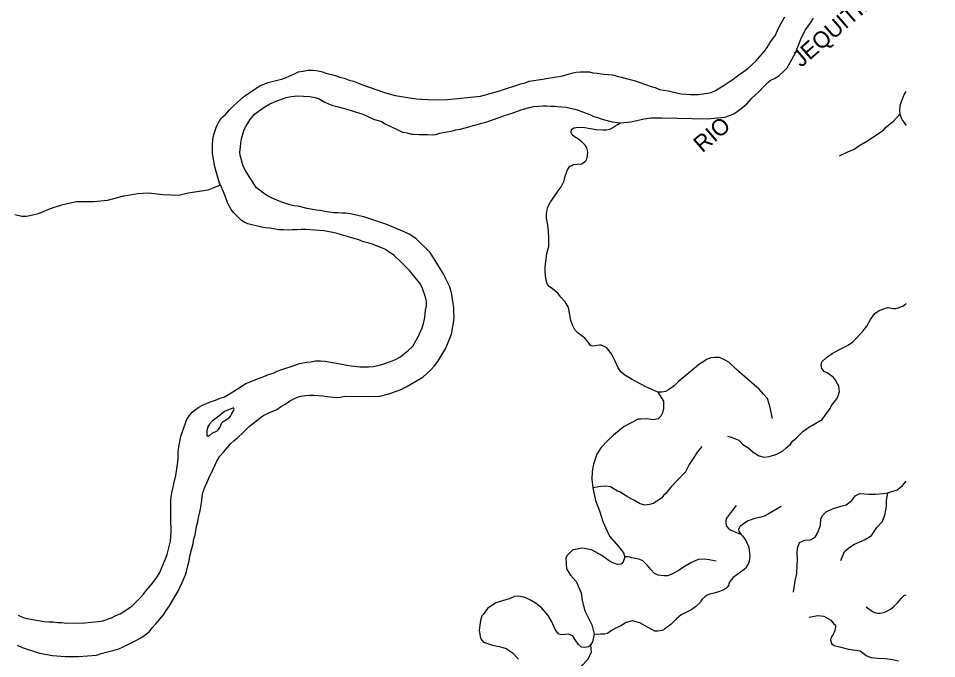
# Model space of a CAD drawing. Extents: x 436.3 to 500.4, y 8231 to 8286.4.
# Drawn here: x 489.18 to 500.37, y 8245.15 to 8252.95 of the extents above; entities that cross this region are included whole.
import ezdxf
from ezdxf.enums import TextEntityAlignment as Align

# ---------------------------------------------------------------- set-up
doc = ezdxf.new("R2010")
doc.units = 0
doc.header["$LTSCALE"] = 0.08
doc.linetypes.add('LONG_DASHED', pattern=[7.5, 6, -1.5])
doc.layers.add('2', color=7, linetype='Continuous', lineweight=25)
doc.layers.add('9', color=7, linetype='LONG_DASHED', lineweight=25)
doc.layers.add('61', color=7, linetype='Continuous')

msp = doc.modelspace()

# ---------------------------------------------------------------- linework, layer by layer
at = {"layer": '2'}
for points in [[(496.5165, 8251.6784), (496.6445, 8251.6907), (496.8052, 8251.7273), (496.8881, 8251.739), (497.0217, 8251.7391), (497.5766, 8251.728), (497.7884, 8251.7467), (497.8436, 8251.7691), (497.8975, 8251.7873), (497.9379, 8251.8145), (498.0231, 8251.8814), (498.0575, 8251.9115), (498.1127, 8251.974), (498.2117, 8252.0645), (498.2614, 8252.1183), (498.3108, 8252.1681), (498.3422, 8252.1953), (498.4006, 8252.2225), (498.4501, 8252.2543), (498.4995, 8252.2996), (498.5489, 8252.3494), (498.5894, 8252.4218), (498.6478, 8252.5304), (498.7153, 8252.6979), (498.7692, 8252.8064), (498.7962, 8252.8426), (498.8322, 8252.8969), (498.8682, 8252.9557)], [(498.2659, 8252.5483), (498.3064, 8252.5981), (498.3379, 8252.6525), (498.4053, 8252.7475), (498.4323, 8252.8018), (498.4548, 8252.8561), (498.4863, 8252.9149)], [(498.4863, 8252.9149), (498.5178, 8252.9692)], [(491.6412, 8250.9216), (491.6325, 8250.942), (491.5734, 8251.1435), (491.5464, 8251.3042), (491.5462, 8251.4128), (491.5506, 8251.4671), (491.5595, 8251.5214), (491.5729, 8251.5712), (491.5908, 8251.6209), (491.6132, 8251.6752), (491.6491, 8251.7295), (491.7029, 8251.7793), (491.7523, 8251.8381), (491.7927, 8251.8788), (491.8466, 8251.924), (491.923, 8251.9963), (492.0647, 8252.0935), (492.1208, 8252.1274), (492.1703, 8252.15), (492.2243, 8252.1681), (492.3864, 8252.2087), (492.4359, 8252.2267), (492.4899, 8252.2493), (492.5439, 8252.2764), (492.5935, 8252.299), (492.652, 8252.308), (492.7061, 8252.3216), (492.7718, 8252.3215), (492.8318, 8252.3123), (492.8862, 8252.2988), (492.9403, 8252.2807), (492.9943, 8252.2671), (493.0439, 8252.2535), (493.098, 8252.2353), (493.152, 8252.2217), (493.2106, 8252.1991), (493.2647, 8252.1854), (493.3232, 8252.1628), (493.3728, 8252.1401), (493.6432, 8252.0494), (493.7731, 8252.0111), (494.027, 8251.9716), (494.2371, 8251.9599), (494.4079, 8251.9644), (494.8116, 8252.0037), (494.8555, 8252.0172), (495.0313, 8252.063), (495.3014, 8252.1531), (495.3555, 8252.1667), (495.405, 8252.1848), (495.5716, 8252.212), (495.6122, 8252.2165), (495.8148, 8252.2528), (495.8688, 8252.2664), (495.9228, 8252.2846), (495.9769, 8252.2936), (496.0309, 8252.2982), (496.1389, 8252.2982), (496.1794, 8252.2892), (496.2334, 8252.2846), (496.3145, 8252.2711), (496.418, 8252.262), (496.4765, 8252.2485), (496.526, 8252.2349), (496.6339, 8252.2078), (496.6834, 8252.1942), (496.8904, 8252.1218), (496.9398, 8252.1082), (496.9938, 8252.0856), (497.0972, 8252.0675), (497.1467, 8252.054), (497.2007, 8252.0449), (497.2546, 8252.0314), (497.3707, 8252.0228), (497.4697, 8252.0229), (497.5526, 8252.0345), (497.6217, 8252.0485), (497.6746, 8252.074), (497.7806, 8252.136), (497.8884, 8252.2085), (497.9423, 8252.2493), (498.0682, 8252.3384), (498.1715, 8252.4351), (498.221, 8252.4895), (498.2659, 8252.5483)], [(492.443, 8251.9884), (492.5052, 8252), (492.5836, 8252.0069), (492.6551, 8252.0045), (492.7335, 8251.9975), (492.7958, 8251.9881), (492.8465, 8251.9719)], [(500, 8252.0616), (499.9877, 8252.0459), (499.9745, 8252.0268), (499.9635, 8251.9944), (499.9417, 8251.946), (499.92, 8251.8849), (499.9184, 8251.8224), (499.9215, 8251.7817)], [(491.5762, 8247.5104), (491.5986, 8247.5554), (491.6345, 8247.6139), (491.6795, 8247.6633), (491.7693, 8247.7713), (491.8052, 8247.8028), (491.8591, 8247.8477), (491.913, 8247.8972), (491.9984, 8247.9827), (492.1583, 8248.1069), (492.2231, 8248.14), (492.331, 8248.1848), (492.3759, 8248.2163), (492.4298, 8248.2478), (492.4838, 8248.2837), (492.5377, 8248.3152), (492.5917, 8248.3376), (492.6232, 8248.3465), (492.6772, 8248.3554), (492.7312, 8248.3598), (492.7807, 8248.3597), (492.8887, 8248.3504), (492.9427, 8248.3412), (493.0508, 8248.3319), (493.1003, 8248.3363), (493.1543, 8248.3452), (493.5325, 8248.3441), (493.5866, 8248.3484), (493.6946, 8248.3752), (493.7982, 8248.411), (493.8522, 8248.4334), (493.9062, 8248.4603), (494.108, 8248.5762), (494.2077, 8248.6671), (494.2526, 8248.7167), (494.2931, 8248.7708), (494.3874, 8248.9332), (494.4143, 8248.9919), (494.4592, 8249.1004), (494.4859, 8249.2632), (494.4903, 8249.3174), (494.4857, 8249.3717), (494.4856, 8249.426), (494.4764, 8249.4758), (494.4718, 8249.5302), (494.4627, 8249.5845), (494.4491, 8249.6389), (494.4354, 8249.6887), (494.354, 8249.8518), (494.1961, 8250.0958), (494.025, 8250.2674), (493.9418, 8250.3209), (493.8799, 8250.3507), (493.6589, 8250.4416), (493.3885, 8250.5325), (493.3344, 8250.5462), (493.2803, 8250.5553), (493.2262, 8250.569), (493.1722, 8250.5781), (493.1316, 8250.5782), (493.0776, 8250.5828), (493.0235, 8250.5829), (492.9695, 8250.5875), (492.9154, 8250.5966), (492.8614, 8250.6103), (492.8073, 8250.6149), (492.6992, 8250.6331), (492.5911, 8250.6604), (492.5371, 8250.665), (492.4876, 8250.6786), (492.438, 8250.6968), (492.3795, 8250.715), (492.2714, 8250.7604), (492.2173, 8250.7876), (492.1678, 8250.8193), (492.1137, 8250.8601), (492.0777, 8250.8918), (491.9532, 8251.089), (491.9242, 8251.1409), (491.9106, 8251.1771), (491.8835, 8251.2858), (491.8789, 8251.322), (491.8878, 8251.3808), (491.8922, 8251.4351), (491.9011, 8251.4849), (491.9145, 8251.5392), (491.9324, 8251.598), (491.9503, 8251.6342), (492.0041, 8251.7202), (492.0582, 8251.785), (492.1295, 8251.8382), (492.1756, 8251.8706), (492.2448, 8251.9099), (492.3208, 8251.9422), (492.443, 8251.9884)], [(492.8465, 8251.9719), (492.9066, 8251.9348), (492.9584, 8251.9095), (493.0124, 8251.8913), (493.062, 8251.8777), (493.1702, 8251.8505), (493.2738, 8251.8142), (493.3234, 8251.8005), (493.3775, 8251.7824), (493.4316, 8251.7597), (493.5082, 8251.7234), (493.6035, 8251.6933), (493.6497, 8251.6655), (493.7021, 8251.6417), (493.8103, 8251.5873), (493.8599, 8251.5646), (493.9185, 8251.5555), (493.9726, 8251.5419), (493.9951, 8251.5418), (494.0629, 8251.5373), (494.1664, 8251.5372), (494.2204, 8251.5326), (494.2655, 8251.5371), (494.3151, 8251.5507), (494.4007, 8251.5687), (494.4547, 8251.5778), (494.5088, 8251.5913), (494.5629, 8251.6004), (494.671, 8251.6275), (494.7205, 8251.6456), (494.7701, 8251.6592), (494.8286, 8251.6727), (494.8782, 8251.6863), (495.0397, 8251.7418), (495.0899, 8251.7633), (495.1439, 8251.7814), (495.198, 8251.795), (495.3061, 8251.8358), (495.4051, 8251.863), (495.4592, 8251.8766), (495.5718, 8251.8857), (495.6168, 8251.8857), (495.6708, 8251.8811), (495.7204, 8251.8811), (495.7519, 8251.8766), (495.8554, 8251.8676), (495.905, 8251.8585), (495.959, 8251.8449), (495.9905, 8251.8359), (496.1416, 8251.778), (496.1931, 8251.7543), (496.2246, 8251.7453), (496.3052, 8251.7201), (496.4159, 8251.6922), (496.5081, 8251.6784), (496.5165, 8251.6784)], [(499.9215, 8251.7817), (499.9371, 8251.7378), (499.9543, 8251.705), (499.9735, 8251.6818), (499.9867, 8251.6627), (500, 8251.6475)], [(492.1418, 8250.4076), (491.9754, 8250.4486), (491.9303, 8250.4666), (491.8987, 8250.4893), (491.8492, 8250.5346), (491.7996, 8250.5844), (491.7725, 8250.6206), (491.7364, 8250.6885), (491.7138, 8250.7519), (491.6862, 8250.8164), (491.6412, 8250.9216)], [(490.9292, 8246.2564), (490.9741, 8246.3642), (490.9921, 8246.4181), (491.0326, 8246.5799), (491.0416, 8246.6877), (491.0416, 8246.7417), (491.0371, 8246.7956), (491.0371, 8247.0654), (491.0415, 8247.1194), (491.0505, 8247.1689), (491.064, 8247.2228), (491.0729, 8247.2768), (491.0999, 8247.3803), (491.1088, 8247.4343), (491.1133, 8247.4883), (491.1222, 8247.5423), (491.1267, 8247.5963), (491.1266, 8247.6504), (491.1311, 8247.7044), (491.1579, 8247.8575), (491.2358, 8248.073), (491.252, 8248.0962), (491.2969, 8248.1502), (491.3328, 8248.1818), (491.3777, 8248.2133), (491.4226, 8248.2358), (491.5304, 8248.2808), (491.5843, 8248.2987), (491.6382, 8248.3212), (491.6922, 8248.3392), (491.7416, 8248.3662), (491.7955, 8248.3977), (491.9527, 8248.5012), (492.1251, 8248.5719), (492.1729, 8248.5865), (492.2268, 8248.609), (492.2853, 8248.6269), (492.3347, 8248.6494), (492.3887, 8248.6718), (492.4381, 8248.6898), (492.4921, 8248.7032), (492.5955, 8248.7391), (492.645, 8248.7526), (492.6945, 8248.7615), (492.7485, 8248.7659), (492.8025, 8248.7793), (492.861, 8248.7792), (492.915, 8248.7745), (493.1267, 8248.7379), (493.1807, 8248.7242), (493.2347, 8248.715), (493.3428, 8248.7057), (493.4509, 8248.7054), (493.5049, 8248.7098), (493.559, 8248.7187), (493.6085, 8248.7321), (493.7165, 8248.7679), (493.775, 8248.7948), (493.829, 8248.8218), (493.928, 8248.9028), (493.9864, 8248.9569), (494.0566, 8249.077), (494.0762, 8249.1285), (494.0986, 8249.1781), (494.1165, 8249.2324), (494.1299, 8249.2866), (494.1388, 8249.3409), (494.1432, 8249.3951), (494.1521, 8249.4494), (494.152, 8249.5037), (494.1429, 8249.5535), (494.1066, 8249.6576), (494.0795, 8249.712), (494.0524, 8249.7483), (493.9467, 8249.8783), (493.838, 8249.9897), (493.7595, 8250.0615), (493.6957, 8250.1065), (493.6461, 8250.1383), (493.6055, 8250.1565), (493.5514, 8250.1747), (493.4973, 8250.1974), (493.4387, 8250.2156), (493.3846, 8250.2293), (493.3305, 8250.252), (493.2269, 8250.2793), (493.1728, 8250.2975), (493.1187, 8250.3112), (493.0646, 8250.3294), (493.0106, 8250.343), (492.9025, 8250.3613), (492.6818, 8250.3797), (492.6278, 8250.3798), (492.5738, 8250.3753), (492.5198, 8250.3754)], [(492.5198, 8250.3754), (492.4658, 8250.371), (492.4118, 8250.3756), (492.3578, 8250.3756), (492.2453, 8250.3939), (492.1913, 8250.3985), (492.1418, 8250.4076)], [(491.419, 8247.1281), (491.428, 8247.1731), (491.4505, 8247.2361), (491.4774, 8247.29), (491.4999, 8247.3485), (491.5537, 8247.4564), (491.5762, 8247.5104)], [(489.1674, 8245.3117), (489.2259, 8245.2848), (489.4371, 8245.213), (489.5945, 8245.1862), (489.7517, 8245.1729), (489.9135, 8245.173), (490.1339, 8245.1892), (490.1876, 8245.2092), (490.3493, 8245.2498), (490.4032, 8245.2678), (490.4571, 8245.2903), (490.6189, 8245.3713), (490.6728, 8245.4028), (490.7267, 8245.4388), (490.7761, 8245.4792), (490.8121, 8245.5241), (490.857, 8245.5736), (490.9469, 8245.6814), (490.9829, 8245.7353), (491.0234, 8245.7892), (491.1313, 8245.9778), (491.1923, 8246.111), (491.2167, 8246.1709), (491.2347, 8246.2248), (491.2437, 8246.2787), (491.2617, 8246.3416), (491.2707, 8246.3955), (491.3112, 8246.5527), (491.3202, 8246.6067), (491.3337, 8246.6561), (491.3517, 8246.7595), (491.3652, 8246.8134), (491.3741, 8246.8673), (491.4011, 8246.9707), (491.4056, 8247.0247), (491.4146, 8247.0742), (491.419, 8247.1281)], [(490.673, 8245.8969), (490.7044, 8245.9329), (490.7404, 8245.9823), (490.8175, 8246.0697), (490.8728, 8246.1455), (490.9022, 8246.198), (490.9292, 8246.2564)], [(489.1765, 8245.6758), (489.2304, 8245.6534), (489.2844, 8245.6354), (489.4957, 8245.5996), (489.5496, 8245.5952), (489.6035, 8245.5952), (489.6575, 8245.5863), (489.7114, 8245.5863), (489.7653, 8245.5819), (489.99, 8245.582), (490.1517, 8245.6001), (490.2101, 8245.6092), (490.3135, 8245.6452), (490.3674, 8245.6722), (490.4213, 8245.6947), (490.4662, 8245.7217), (490.5202, 8245.7576), (490.5696, 8245.7936), (490.673, 8245.8969)]]:
    msp.add_lwpolyline(points, dxfattribs=at)
msp.add_lwpolyline([(491.603, 8248.0881), (491.5472, 8248.0463), (491.5089, 8248.0061), (491.4845, 8247.9659), (491.4776, 8247.9258), (491.4777, 8247.8647), (491.5056, 8247.8647), (491.5422, 8247.8961), (491.6014, 8247.9257), (491.6205, 8247.9414), (491.6363, 8247.9641), (491.6589, 8248.0199), (491.6746, 8248.0391), (491.7496, 8248.0827), (491.7634, 8248.1019), (491.7826, 8248.135), (491.8035, 8248.1681), (491.8087, 8248.1892), (491.8003, 8248.2059), (491.6924, 8248.1589)], close=True, dxfattribs=at)
at = {"layer": '9'}
msp.add_line((496.4832, 8251.6558), (496.5165, 8251.6784), dxfattribs=at)
for points in [[(499.1864, 8251.2742), (499.2886, 8251.3232), (499.3639, 8251.3558), (499.4231, 8251.3992), (499.4984, 8251.4426), (499.5522, 8251.4751), (499.7243, 8251.5945), (499.7404, 8251.6162), (499.848, 8251.7029), (499.9215, 8251.7817)], [(496.9728, 8248.3935), (496.8268, 8248.4612), (496.7644, 8248.4925), (496.6601, 8248.5498), (496.5715, 8248.6021), (496.5246, 8248.6386), (496.4828, 8248.7014), (496.4514, 8248.7747), (496.4095, 8248.8637), (496.3453, 8248.9383), (496.2827, 8248.9697), (496.2618, 8248.9697), (496.231, 8248.9653), (496.2069, 8248.9586), (496.1785, 8248.9565), (496.161, 8248.9608), (496.1436, 8248.9718), (496.1326, 8248.9916), (496.1129, 8249.0223), (496.0845, 8249.0553), (496.0625, 8249.0685), (496.0034, 8249.1146), (495.9618, 8249.1562), (495.9377, 8249.2025), (495.9136, 8249.2705), (495.9004, 8249.3387), (495.8827, 8249.4243), (495.8795, 8249.4363), (495.8422, 8249.4978), (495.7897, 8249.555), (495.7546, 8249.6033), (495.6889, 8249.6561), (495.6495, 8249.6825), (495.6254, 8249.7154), (495.61, 8249.7593), (495.6033, 8249.8143), (495.5988, 8249.8737), (495.5986, 8249.9192), (495.6202, 8250.0862), (495.644, 8250.1719), (495.6438, 8250.2752), (495.6415, 8250.3587), (495.6327, 8250.4313), (495.6171, 8250.5163), (495.617, 8250.5691), (495.6279, 8250.6439), (495.6584, 8250.7098), (495.6715, 8250.7229), (495.7586, 8250.8483), (495.7936, 8250.8988), (495.8266, 8250.9616), (495.8483, 8251.0385), (495.8701, 8251.1067), (495.8985, 8251.1484), (495.9225, 8251.1594), (495.9465, 8251.1705), (496.0411, 8251.1802), (496.0739, 8251.1977), (496.0936, 8251.2132), (496.1066, 8251.2373), (496.1153, 8251.2747), (496.1174, 8251.3231), (496.1065, 8251.3737), (496.0868, 8251.4066), (496.0452, 8251.4462), (496.0037, 8251.477), (495.9577, 8251.5055), (495.9293, 8251.5319), (495.9162, 8251.5605), (495.9205, 8251.5957), (495.9489, 8251.6176), (496.0035, 8251.6264), (496.0823, 8251.6221), (496.2199, 8251.5958), (496.3007, 8251.5936), (496.3444, 8251.5914), (496.3859, 8251.6003), (496.4122, 8251.6113), (496.4471, 8251.6377), (496.4832, 8251.6558)], [(489.1376, 8250.5598), (489.2231, 8250.5425), (489.2811, 8250.5425), (489.3563, 8250.5563), (489.4237, 8250.5745), (489.5705, 8250.6357), (489.7218, 8250.6813), (489.8883, 8250.7193), (490.1003, 8250.7192), (490.2666, 8250.7345), (490.4633, 8250.7877), (490.6373, 8250.818), (490.766, 8250.8256), (490.9401, 8250.8027), (491.1369, 8250.7949), (491.2504, 8250.8253), (491.4926, 8250.8632), (491.576, 8250.8936), (491.6412, 8250.9216)], [(497.8207, 8247.8609), (497.8666, 8247.8472), (497.9581, 8247.8107), (498.0086, 8247.7557), (498.0682, 8247.7192), (498.1324, 8247.6642), (498.2057, 8247.6184), (498.2699, 8247.6049), (498.3294, 8247.6097), (498.4118, 8247.6375), (498.4896, 8247.6745), (498.5354, 8247.7161), (498.5871, 8247.7629), (498.614, 8247.7991), (498.6588, 8247.8353), (498.7396, 8247.9167), (498.8203, 8247.9711), (498.9728, 8248.0617), (499.0713, 8248.1973), (499.0893, 8248.2335), (499.152, 8248.3148), (499.1699, 8248.3509), (499.1878, 8248.4051), (499.1787, 8248.4682), (499.1607, 8248.4953), (499.1337, 8248.5493), (499.1068, 8248.5763), (499.0349, 8248.6302), (498.9989, 8248.6481), (498.972, 8248.6841), (498.963, 8248.7292), (498.9719, 8248.7653), (499.0256, 8248.8196), (499.0974, 8248.865), (499.1781, 8248.9104), (499.2678, 8248.9558), (499.2947, 8248.974), (499.3491, 8249.0101), (499.3978, 8249.0576), (499.4709, 8249.139), (499.5187, 8249.2002), (499.5635, 8249.2817), (499.6173, 8249.3542), (499.6711, 8249.3904), (499.7696, 8249.4266)], [(499.7696, 8249.4266), (499.8005, 8249.4239), (499.8398, 8249.4157), (499.8662, 8249.4164), (499.9047, 8249.4246), (499.9609, 8249.447), (499.99, 8249.4666), (500, 8249.4753)], [(498.3696, 8248.0725), (498.3382, 8248.224), (498.3069, 8248.3181), (498.2599, 8248.3702), (498.2079, 8248.4328), (498.0619, 8248.5579), (497.9317, 8248.6726), (497.8379, 8248.7612), (497.7911, 8248.7873), (497.7234, 8248.8185), (497.6661, 8248.8183), (497.6192, 8248.813), (497.5672, 8248.7919), (497.5308, 8248.7709), (497.4841, 8248.7393), (497.3645, 8248.6448), (497.2917, 8248.5818), (497.2241, 8248.5241), (497.1721, 8248.4717), (497.1029, 8248.4252), (497.0664, 8248.4041), (497.0196, 8248.3936), (496.9728, 8248.3935)], [(496.9728, 8248.3935), (497.0417, 8248.2876), (497.0403, 8248.1961), (497.03, 8248.1438), (497.0092, 8248.102), (496.978, 8248.0706), (496.9208, 8248.0601), (496.8375, 8248.0703), (496.7646, 8248.065), (496.7334, 8248.0649), (496.6294, 8248.0124), (496.5617, 8247.9758), (496.4317, 8247.8712), (496.3588, 8247.8032), (496.2808, 8247.7197), (496.2287, 8247.6415), (496.187, 8247.5163), (496.1713, 8247.4278), (496.1661, 8247.334), (496.1783, 8247.2274)], [(497.5093, 8247.7312), (497.4544, 8247.6668), (497.3949, 8247.5747), (497.3537, 8247.5148), (497.3079, 8247.4228), (497.207, 8247.3169), (497.1337, 8247.2434), (497.1045, 8247.2099), (497.0723, 8247.1639), (497.0402, 8247.1363), (497.022, 8247.1087), (497.0036, 8247.095), (496.9669, 8247.072), (496.9531, 8247.0628), (496.921, 8247.0398), (496.9165, 8247.0398), (496.8706, 8247.0259), (496.8156, 8247.0167), (496.756, 8247.035), (496.6781, 8247.0807), (496.5955, 8247.122), (496.5176, 8247.177), (496.4809, 8247.1907), (496.3938, 8247.2412), (496.3342, 8247.2503), (496.2791, 8247.2457), (496.2333, 8247.2366), (496.1783, 8247.2274)], [(499.7763, 8247.1696), (499.888, 8247.2051), (499.9551, 8247.2558), (499.9824, 8247.2919), (500, 8247.3125)], [(496.1783, 8247.2274), (496.2129, 8247.0735), (496.2597, 8246.9485), (496.3007, 8246.8208), (496.3372, 8246.7375), (496.384, 8246.6386), (496.4933, 8246.5136), (496.5557, 8246.4356), (496.5714, 8246.3887)], [(498.6252, 8245.9574), (498.6476, 8246.0974), (498.6644, 8246.187), (498.67, 8246.2878), (498.6755, 8246.355), (498.6699, 8246.4334), (498.6755, 8246.495), (498.6979, 8246.5623), (498.765, 8246.5905), (498.8311, 8246.5966), (498.8896, 8246.6272), (498.9158, 8246.675), (498.9549, 8246.7704), (498.9603, 8246.852), (498.9845, 8246.8966), (499.0219, 8246.9387), (499.1002, 8246.9726), (499.2007, 8247.0066), (499.2678, 8247.0236), (499.3348, 8247.0743), (499.3752, 8247.1303), (499.4342, 8247.1608), (499.5415, 8247.1535), (499.6198, 8247.1538), (499.7148, 8247.1596), (499.7763, 8247.1696)], [(499.201, 8246.3455), (499.2457, 8246.4521), (499.3016, 8246.4971), (499.3687, 8246.5421), (499.4972, 8246.5986), (499.5754, 8246.6493), (499.6425, 8246.7447), (499.7095, 8246.8177), (499.743, 8246.9132), (499.7596, 8247.0085), (499.7595, 8247.0758), (499.7763, 8247.1696)], [(497.9256, 8247.0151), (497.8836, 8246.9561), (497.8444, 8246.9083), (497.8109, 8246.8605), (497.8025, 8246.8296), (497.7996, 8246.796), (497.8081, 8246.7624), (497.8361, 8246.7316), (497.8612, 8246.7148), (497.9228, 8246.6898), (497.9592, 8246.673), (497.9852, 8246.6647)], [(498.4747, 8247.0002), (498.3761, 8246.9468), (498.2793, 8246.8877), (498.2269, 8246.87), (498.1423, 8246.8522), (498.0723, 8246.8258), (498.0023, 8246.7817), (497.9732, 8246.7524), (497.9565, 8246.7252), (497.9586, 8246.7027), (497.9852, 8246.6647)], [(497.9852, 8246.6647), (498.0052, 8246.6444), (498.0461, 8246.5862), (498.0781, 8246.5131), (498.0869, 8246.4781), (498.0898, 8246.4315), (498.0927, 8246.3994), (498.084, 8246.3351), (498.0752, 8246.3087), (498.0431, 8246.2503), (498.0257, 8246.2356), (497.8885, 8246.136), (497.8641, 8246.108), (497.8407, 8246.0758), (497.8319, 8246.0408), (497.8173, 8246.0174), (497.7998, 8246.0028), (497.7649, 8245.9823), (497.724, 8245.9676), (497.6597, 8245.9442), (497.6044, 8245.9324), (497.5752, 8245.9206), (497.5489, 8245.903), (497.5138, 8245.8739), (497.4963, 8245.8475), (497.4876, 8245.8329), (497.435, 8245.7832), (497.3884, 8245.7481), (497.256, 8245.6831), (497.1992, 8245.6313), (497.132, 8245.5641), (497.0855, 8245.5331), (497.0544, 8245.5072), (497.0234, 8245.4917), (496.9717, 8245.4814), (496.9356, 8245.4814), (496.889, 8245.5072), (496.8168, 8245.5485), (496.7548, 8245.5846), (496.6598, 8245.6096), (496.5874, 8245.589), (496.5202, 8245.5477), (496.4529, 8245.5167), (496.4064, 8245.491), (496.3599, 8245.4549), (496.3237, 8245.4446), (496.2772, 8245.4447), (496.2366, 8245.4398), (496.1983, 8245.4451)], [(496.5714, 8246.3887), (496.5504, 8246.3263), (496.5244, 8246.3002), (496.4827, 8246.295), (496.3942, 8246.3263), (496.2901, 8246.4044), (496.165, 8246.4721), (496.0504, 8246.4931), (495.967, 8246.4775), (495.9358, 8246.4724), (495.8628, 8246.3996), (495.8523, 8246.3736), (495.8574, 8246.2436), (495.9095, 8246.1654), (495.9772, 8246.0872), (496.038, 8245.9491), (496.0483, 8245.8554), (496.0846, 8245.7304), (496.1574, 8245.5847), (496.1678, 8245.5587), (496.1983, 8245.4451)], [(497.6817, 8246.3368), (497.5984, 8246.3533), (497.5358, 8246.3615), (497.465, 8246.3573), (497.4192, 8246.3363), (497.3734, 8246.3154), (497.2858, 8246.261), (497.2317, 8246.2276), (497.1441, 8246.1775), (497.0899, 8246.1566), (497.044, 8246.1566), (496.9774, 8246.1648), (496.9315, 8246.1857), (496.8857, 8246.2355), (496.8483, 8246.2814), (496.7899, 8246.3397), (496.7525, 8246.3564), (496.6982, 8246.3689), (496.6524, 8246.3771), (496.6148, 8246.3896), (496.5714, 8246.3887)], [(496.1571, 8245.3194), (496.1258, 8245.2933), (496.0789, 8245.283), (496.0425, 8245.2882), (496.006, 8245.3196), (495.9644, 8245.3768), (495.9384, 8245.4238), (495.881, 8245.4447), (495.7977, 8245.4396), (495.7664, 8245.4449), (495.7195, 8245.5022), (495.6825, 8245.5957), (495.6357, 8245.6739), (495.5575, 8245.7625), (495.4899, 8245.8199), (495.4221, 8245.8617), (495.3648, 8245.8878), (495.3388, 8245.8983), (495.271, 8245.9089), (495.2188, 8245.9039), (495.2084, 8245.8987), (495.1615, 8245.878), (494.9998, 8245.8266), (494.9841, 8245.8215), (494.8955, 8245.7593), (494.8433, 8245.6867), (494.8276, 8245.6711), (494.8119, 8245.614), (494.8067, 8245.5828), (494.7962, 8245.4945), (494.8013, 8245.4424), (494.8117, 8245.3956), (494.8273, 8245.3747), (494.8481, 8245.3486), (494.8951, 8245.3329), (494.9576, 8245.3118), (495.041, 8245.2959), (495.1243, 8245.2696), (495.2025, 8245.2173), (495.2753, 8245.1391)], [(499.5107, 8245.7773), (499.588, 8245.7217), (499.6177, 8245.7113), (499.6472, 8245.703), (499.683, 8245.7031), (499.725, 8245.7117), (499.7608, 8245.7266), (499.807, 8245.752), (499.849, 8245.7838), (499.8975, 8245.8302), (499.9353, 8245.8787), (499.9604, 8245.9063), (499.9731, 8245.9168), (500, 8245.9266)], [(498.815, 8245.6547), (498.9221, 8245.6748), (498.9954, 8245.6637), (499.08, 8245.6161), (499.1138, 8245.5766), (499.1391, 8245.5542), (499.1391, 8245.5316), (499.1307, 8245.492), (499.1082, 8245.4412), (499.0856, 8245.4073), (499.0771, 8245.3762), (499.0884, 8245.3311), (499.1222, 8245.3087), (499.204, 8245.2863), (499.2971, 8245.2641), (499.438, 8245.2419), (499.4719, 8245.2195), (499.4944, 8245.1998), (499.5197, 8245.1802), (499.5734, 8245.1634), (499.6551, 8245.1524), (499.7453, 8245.1499), (499.8299, 8245.136), (499.906, 8245.1222)], [(496.1983, 8245.4451), (496.178, 8245.3505), (496.1571, 8245.3194)], [(496.5133, 8244.0823), (496.4978, 8244.0772), (496.4462, 8244.0565), (496.379, 8244.0566), (496.3633, 8244.0514), (496.2548, 8244.0723), (496.1619, 8244.1292), (496.0637, 8244.212), (495.9655, 8244.331), (495.9243, 8244.4189), (495.9032, 8244.5444), (495.8981, 8244.6425), (495.8983, 8244.7613), (495.9243, 8244.88), (495.9657, 8244.9625), (496.0589, 8245.0708), (496.1262, 8245.1481), (496.1624, 8245.2306), (496.1602, 8245.2649), (496.1571, 8245.3194)]]:
    msp.add_lwpolyline(points, dxfattribs=at)

# ---------------------------------------------------------------- texts
at = {"layer": '61'}
msp.add_text('RIO               JEQUITINHONHA', height=0.2, rotation=40.847, dxfattribs=at).set_placement((498.9423, 8252.5405), align=Align.CENTER)

doc.saveas('drawing.dxf')
